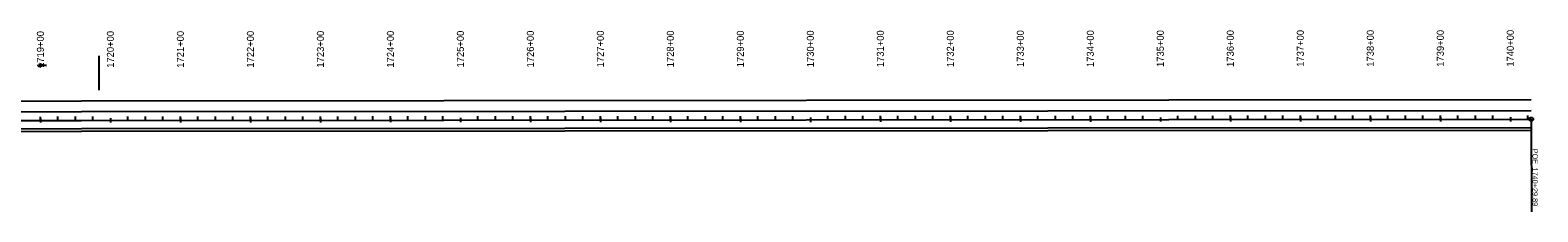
# Model space of a CAD drawing. Extents: x 16513048 to 16518780, y 7009856 to 7010869.
# Drawn here: x 16516626 to 16518780, y 7010229 to 7010488 of the extents above; entities that cross this region are included whole.
import ezdxf

# ---------------------------------------------------------------- set-up
doc = ezdxf.new("R2010")
doc.units = 0
for name, color, linetype in [('dsnNonPlotable', 7, 'Continuous'), ('Level 2', 7, 'Continuous'), ('SheetBorder', 7, 'Continuous'), ('tdCoTitleBlock', 7, 'Continuous')]:
    doc.layers.add(name, color=color, linetype=linetype)

msp = doc.modelspace()

# ---------------------------------------------------------------- linework, layer by layer
at = {"layer": 'dsnNonPlotable'}
for p, q in [((16513050.3, 7010352.9), (16516699.6, 7010359.3)), ((16516699.6, 7010359.3), (16518770.7, 7010360.9))]:
    msp.add_line(p, q, dxfattribs=at)
for points in [[(16513050.2, 7010380.9), (16516699.6, 7010387.3), (16518770.7, 7010388.9)], [(16518770.7, 7010372.9), (16516699.6, 7010371.3), (16513050.3, 7010364.9)], [(16518770.7, 7010348.9), (16516699.6, 7010347.3), (16513050.3, 7010340.9)], [(16518770.7, 7010344.9), (16516699.6, 7010343.3), (16513050.3, 7010336.9)]]:
    msp.add_lwpolyline(points, dxfattribs=at)
at = {"layer": 'Level 2'}
for p, q in [((16516724.4, 7010402.6), (16516724.4, 7010451.5)), ((16518770.7, 7010360.9), (16518770.8, 7010228.9)), ((16518770.8, 7010228.9), (16518770.8, 7010228.9))]:
    msp.add_line(p, q, dxfattribs=at)
msp.add_circle((16518770.7, 7010360.9), 2.67, dxfattribs=at)
for centre, radius, start, end in [((16516631.5, 7010438), 8.22, 341.2666, 16.7334), ((16516649, 7010416.4), 21.3, 89.0176, 117.0725), ((16516649.7, 7010459), 21.3, 240.9275, 268.9824)]:
    msp.add_arc(centre, radius, start, end, dxfattribs=at)
at = {"layer": 'SheetBorder'}
for p, q in [((16516665.8, 7010359.2), (16516665.8, 7010364.7)), ((16516690.8, 7010359.3), (16516690.8, 7010364.7)), ((16516715.8, 7010359.3), (16516715.8, 7010364.7)), ((16516765.8, 7010359.3), (16516765.8, 7010364.8)), ((16516790.8, 7010359.3), (16516790.8, 7010364.8)), ((16516815.8, 7010359.4), (16516815.8, 7010364.8)), ((16516865.8, 7010359.4), (16516865.8, 7010364.9)), ((16516890.8, 7010359.4), (16516890.8, 7010364.9)), ((16516915.8, 7010359.4), (16516915.8, 7010364.9)), ((16516965.8, 7010359.5), (16516965.8, 7010364.9)), ((16516990.8, 7010359.5), (16516990.8, 7010365)), ((16517015.8, 7010359.5), (16517015.8, 7010365)), ((16517065.8, 7010359.6), (16517065.8, 7010365)), ((16517090.8, 7010359.6), (16517090.8, 7010365)), ((16517115.8, 7010359.6), (16517115.8, 7010365.1)), ((16517165.8, 7010359.6), (16517165.8, 7010365.1)), ((16517190.8, 7010359.7), (16517190.8, 7010365.1)), ((16517215.8, 7010359.7), (16517215.8, 7010365.1)), ((16517265.8, 7010359.7), (16517265.8, 7010365.2)), ((16517290.8, 7010359.7), (16517290.8, 7010365.2)), ((16517315.8, 7010359.8), (16517315.8, 7010365.2)), ((16517365.8, 7010359.8), (16517365.8, 7010365.3)), ((16517390.8, 7010359.8), (16517390.8, 7010365.3)), ((16517415.8, 7010359.8), (16517415.8, 7010365.3)), ((16517465.8, 7010359.9), (16517465.8, 7010365.3)), ((16517490.8, 7010359.9), (16517490.8, 7010365.4)), ((16517515.8, 7010359.9), (16517515.8, 7010365.4)), ((16517565.8, 7010360), (16517565.8, 7010365.4)), ((16517590.8, 7010360), (16517590.8, 7010365.4)), ((16517615.8, 7010360), (16517615.8, 7010365.5)), ((16517665.8, 7010360), (16517665.8, 7010365.5)), ((16517690.8, 7010360.1), (16517690.8, 7010365.5)), ((16517715.8, 7010360.1), (16517715.8, 7010365.5)), ((16517765.8, 7010360.1), (16517765.8, 7010365.6)), ((16517790.8, 7010360.1), (16517790.8, 7010365.6)), ((16517815.8, 7010360.2), (16517815.8, 7010365.6)), ((16517865.8, 7010360.2), (16517865.8, 7010365.7)), ((16517890.8, 7010360.2), (16517890.8, 7010365.7)), ((16517915.8, 7010360.3), (16517915.8, 7010365.7)), ((16517965.8, 7010360.3), (16517965.8, 7010365.8)), ((16517990.8, 7010360.3), (16517990.8, 7010365.8)), ((16518015.8, 7010360.3), (16518015.8, 7010365.8)), ((16518065.8, 7010360.4), (16518065.8, 7010365.8)), ((16518090.8, 7010360.4), (16518090.8, 7010365.9)), ((16518115.8, 7010360.4), (16518115.8, 7010365.9)), ((16518165.8, 7010360.5), (16518165.8, 7010365.9)), ((16518190.8, 7010360.5), (16518190.8, 7010365.9)), ((16518215.8, 7010360.5), (16518215.8, 7010366)), ((16518265.8, 7010360.5), (16518265.8, 7010366)), ((16518290.8, 7010360.6), (16518290.8, 7010366)), ((16518315.8, 7010360.6), (16518315.8, 7010366)), ((16518365.8, 7010360.6), (16518365.8, 7010366.1)), ((16518390.8, 7010360.6), (16518390.8, 7010366.1)), ((16518415.8, 7010360.7), (16518415.8, 7010366.1)), ((16518465.8, 7010360.7), (16518465.8, 7010366.2)), ((16518490.8, 7010360.7), (16518490.8, 7010366.2)), ((16518515.8, 7010360.7), (16518515.8, 7010366.2)), ((16518565.8, 7010360.8), (16518565.8, 7010366.2)), ((16518590.8, 7010360.8), (16518590.8, 7010366.3)), ((16518615.8, 7010360.8), (16518615.8, 7010366.3)), ((16518665.8, 7010360.9), (16518665.8, 7010366.3)), ((16518690.8, 7010360.9), (16518690.8, 7010366.3)), ((16518715.8, 7010360.9), (16518715.8, 7010366.4)), ((16518765.8, 7010360.9), (16518765.8, 7010366.4)), ((16516640.8, 7010362.2), (16516640.8, 7010356.1)), ((16516740.8, 7010362.4), (16516740.8, 7010356.2)), ((16516840.8, 7010362.4), (16516840.8, 7010356.3)), ((16516940.8, 7010362.5), (16516940.8, 7010356.4)), ((16517040.8, 7010362.6), (16517040.8, 7010356.5)), ((16517140.8, 7010362.7), (16517140.8, 7010356.6)), ((16517240.8, 7010362.8), (16517240.8, 7010356.6)), ((16517340.8, 7010362.8), (16517340.8, 7010356.7)), ((16517440.8, 7010362.9), (16517440.8, 7010356.8)), ((16517540.8, 7010363), (16517540.8, 7010356.9)), ((16517640.8, 7010363.1), (16517640.8, 7010357)), ((16517740.8, 7010363.2), (16517740.8, 7010357)), ((16517840.8, 7010363.3), (16517840.8, 7010357.1)), ((16517940.8, 7010363.3), (16517940.8, 7010357.2)), ((16518040.8, 7010363.4), (16518040.8, 7010357.3)), ((16518140.8, 7010363.5), (16518140.8, 7010357.4)), ((16518240.8, 7010363.6), (16518240.8, 7010357.5)), ((16518340.8, 7010363.7), (16518340.8, 7010357.5)), ((16518440.8, 7010363.7), (16518440.8, 7010357.6)), ((16518540.8, 7010363.8), (16518540.8, 7010357.7)), ((16518640.8, 7010363.9), (16518640.8, 7010357.8)), ((16518740.8, 7010364), (16518740.8, 7010357.9))]:
    msp.add_line(p, q, dxfattribs=at)
at = {"layer": 'tdCoTitleBlock'}
for p, q in [((16516640.8, 7010359.2), (16516640.8, 7010364.6)), ((16516840.8, 7010359.4), (16516840.8, 7010364.8)), ((16516940.8, 7010359.5), (16516940.8, 7010364.9)), ((16517040.8, 7010359.5), (16517040.8, 7010365)), ((16517140.8, 7010359.6), (16517140.8, 7010365.1)), ((16517340.8, 7010359.8), (16517340.8, 7010365.2)), ((16517440.8, 7010359.9), (16517440.8, 7010365.3)), ((16517540.8, 7010359.9), (16517540.8, 7010365.4)), ((16517640.8, 7010360), (16517640.8, 7010365.5)), ((16517840.8, 7010360.2), (16517840.8, 7010365.7)), ((16517940.8, 7010360.3), (16517940.8, 7010365.7)), ((16518040.8, 7010360.4), (16518040.8, 7010365.8)), ((16518140.8, 7010360.4), (16518140.8, 7010365.9)), ((16518340.8, 7010360.6), (16518340.8, 7010366.1)), ((16518440.8, 7010360.7), (16518440.8, 7010366.1)), ((16518540.8, 7010360.8), (16518540.8, 7010366.2)), ((16518640.8, 7010360.8), (16518640.8, 7010366.3)), ((16516740.8, 7010362.4), (16516740.8, 7010356.2)), ((16517240.8, 7010362.8), (16517240.8, 7010356.6)), ((16517740.8, 7010363.2), (16517740.8, 7010357)), ((16518240.8, 7010363.6), (16518240.8, 7010357.5)), ((16518740.8, 7010364), (16518740.8, 7010357.9))]:
    msp.add_line(p, q, dxfattribs=at)

# ---------------------------------------------------------------- texts
at = {"layer": 'Level 2'}
for s, p in [('POE ', (16518772.4, 7010318.9)), ('1740+29.89', (16518772.4, 7010292))]:
    msp.add_text(s, height=7.5, rotation=270.0459, dxfattribs=at).set_placement(p)
at = {"layer": 'SheetBorder'}
for s, rotation, p in [('1719+00', 90.0999, (16516645.7, 7010434.2)), ('1720+00', 90.0459, (16516745.7, 7010434.3)), ('1721+00', 90.0459, (16516845.7, 7010434.4)), ('1722+00', 90.0459, (16516945.7, 7010434.5)), ('1723+00', 90.0459, (16517045.7, 7010434.6)), ('1724+00', 90.0459, (16517145.7, 7010434.6)), ('1725+00', 90.0459, (16517245.7, 7010434.7)), ('1726+00', 90.0459, (16517345.7, 7010434.8)), ('1727+00', 90.0459, (16517445.7, 7010434.9)), ('1728+00', 90.0459, (16517545.7, 7010435)), ('1729+00', 90.0459, (16517645.7, 7010435)), ('1730+00', 90.0459, (16517745.7, 7010435.1)), ('1731+00', 90.0459, (16517845.7, 7010435.2)), ('1732+00', 90.0459, (16517945.7, 7010435.3)), ('1733+00', 90.0459, (16518045.7, 7010435.4)), ('1734+00', 90.0459, (16518145.7, 7010435.4)), ('1735+00', 90.0459, (16518245.7, 7010435.5)), ('1736+00', 90.0459, (16518345.7, 7010435.6)), ('1737+00', 90.0459, (16518445.7, 7010435.7)), ('1738+00', 90.0459, (16518545.7, 7010435.8)), ('1739+00', 90.0459, (16518645.7, 7010435.8)), ('1740+00', 90.0459, (16518745.7, 7010435.9))]:
    msp.add_text(s, height=10.02, rotation=rotation, dxfattribs=at).set_placement(p)
at = {"layer": 'tdCoTitleBlock'}
for s, p in [('1720+00', (16516745.7, 7010434.3)), ('1725+00', (16517245.7, 7010434.7)), ('1730+00', (16517745.7, 7010435.1)), ('1735+00', (16518245.7, 7010435.5)), ('1740+00', (16518745.7, 7010435.9))]:
    msp.add_text(s, height=10.02, rotation=90.0459, dxfattribs=at).set_placement(p)

doc.saveas('drawing.dxf')
